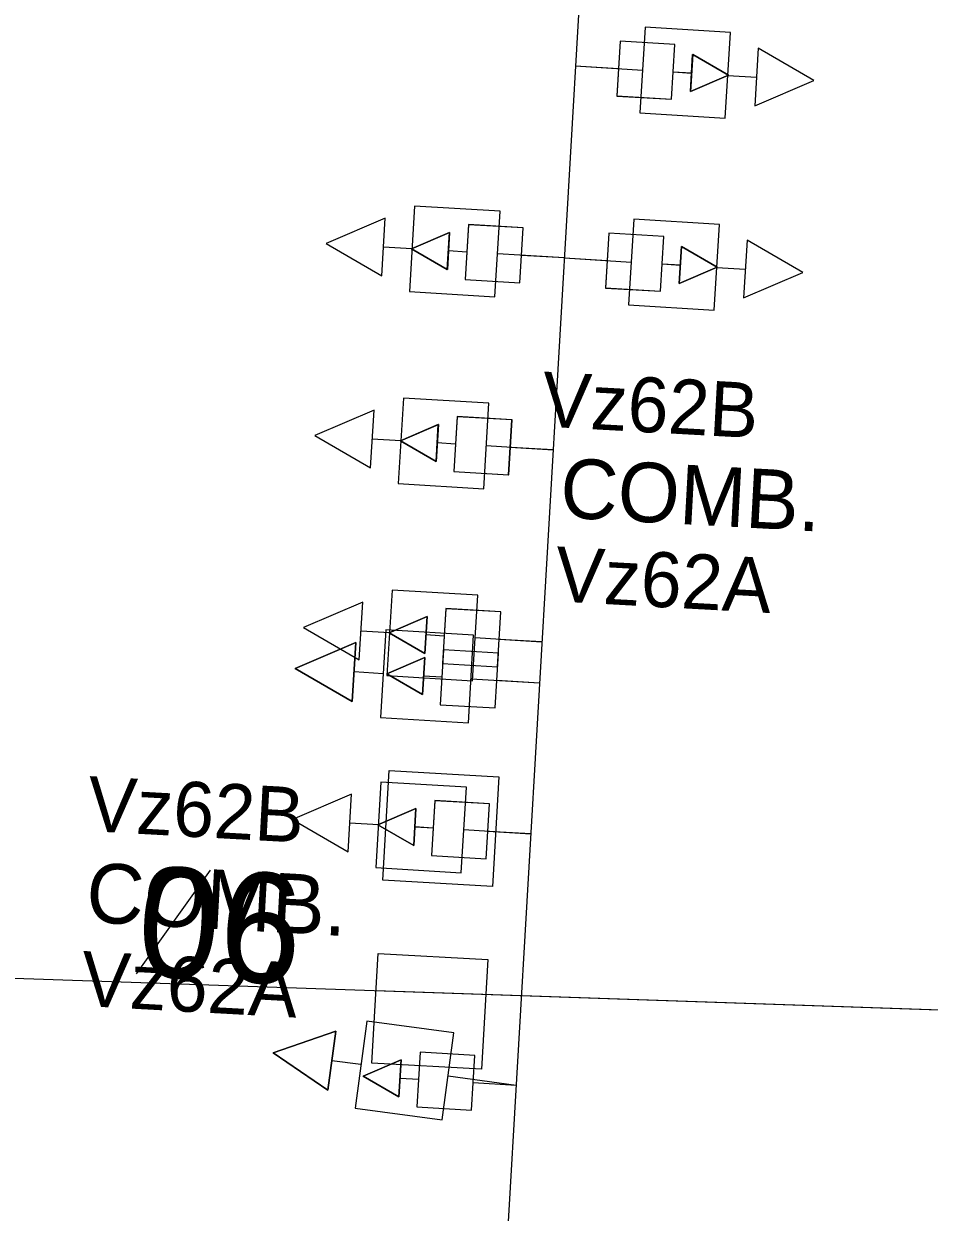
# Model space of a CAD drawing. Extents: x 647787 to 668496, y 640478 to 654412.
# Drawn here: x 661587 to 661636.4, y 647292 to 647356.9 of the extents above; entities that cross this region are included whole.
import ezdxf

# ---------------------------------------------------------------- set-up
doc = ezdxf.new("R2010")
doc.units = 0
for name, color, linetype in [('Default', 7, 'Continuous'), ('TEMP_DETECTION ZONE_Stage 2', 7, 'Continuous'), ('TEMP_DETECTION ZONE_STAGE 3', 7, 'Continuous'), ('TEMP_DETECTION_ZONE_STAGE 4', 7, 'Continuous'), ('TEMP_SIGNAL_HEAD_PED STAGES 1C', 7, 'Continuous'), ('TEMP_SIGNAL_HEAD_STAGE 2', 7, 'Continuous'), ('TEMP_SIGNAL_HEAD_STAGE 2 SHILO', 7, 'Continuous'), ('TEMP_SIGNAL_HEAD_STAGE 3 SHILO', 7, 'Continuous'), ('TEMP_SIGNAL_HEAD_STAGE 4 SHILO', 7, 'Continuous'), ('TEMP_SIGNAL_POLE_STAGE 2-3', 7, 'Continuous')]:
    doc.layers.add(name, color=color, linetype=linetype)

msp = doc.modelspace()

# ---------------------------------------------------------------- linework, layer by layer
at = {"layer": 'Default'}
msp.add_line((661593.14, 647304.985), (661597.182, 647310.641), dxfattribs=at)
msp.add_line((661593.14, 647304.985), (661597.182, 647310.641), dxfattribs=at)
for points in [[(662136.439, 647331.769), (661882.019, 647294.613), (661114.402, 647320.889)], [(661761.55, 647298.737), (661606.212, 647304.054)], [(661761.55, 647298.737), (661606.212, 647304.054)]]:
    msp.add_lwpolyline(points, dxfattribs=at)
at = {"layer": 'TEMP_DETECTION ZONE_STAGE 3'}
for points in [[(661612.588, 647309.755), (661606.598, 647310.095), (661606.938, 647316.085), (661612.928, 647315.745)], [(661611.985, 647299.773), (661605.995, 647300.113), (661606.335, 647306.103), (661612.326, 647305.763)]]:
    msp.add_lwpolyline(points, close=True, dxfattribs=at)
at = {"layer": 'TEMP_DETECTION_ZONE_STAGE 4'}
for points in [[(661612.588, 647309.755), (661606.598, 647310.095), (661606.938, 647316.085), (661612.928, 647315.745)], [(661611.985, 647299.773), (661605.995, 647300.113), (661606.335, 647306.103), (661612.326, 647305.763)]]:
    msp.add_lwpolyline(points, close=True, dxfattribs=at)
at = {"layer": 'TEMP_SIGNAL_HEAD_PED STAGES 1C'}
for points in [[(661612.721, 647319.498), (661612.902, 647322.493), (661609.907, 647322.673), (661609.727, 647319.679)], [(661612.721, 647319.498), (661612.902, 647322.493), (661609.907, 647322.673), (661609.727, 647319.679)], [(661606.807, 647321.358), (661608.758, 647320.227), (661608.88, 647322.246)], [(661606.807, 647321.358), (661608.758, 647320.227), (661608.88, 647322.246)], [(661611.439, 647297.535), (661611.619, 647300.53), (661608.625, 647300.711), (661608.444, 647297.716)], [(661611.439, 647297.535), (661611.619, 647300.53), (661608.625, 647300.711), (661608.444, 647297.716)], [(661605.524, 647299.395), (661607.475, 647298.264), (661607.597, 647300.284)], [(661605.524, 647299.395), (661607.475, 647298.264), (661607.597, 647300.284)]]:
    msp.add_lwpolyline(points, close=True, dxfattribs=at)
for points in [[(661608.88, 647322.246), (661608.758, 647320.227), (661606.807, 647321.358), (661608.88, 647322.246)], [(661608.88, 647322.246), (661608.758, 647320.227), (661606.807, 647321.358), (661608.88, 647322.246)], [(661609.817, 647321.176), (661608.819, 647321.236)], [(661609.817, 647321.176), (661608.819, 647321.236)], [(661615.152, 647320.854), (661612.812, 647320.995)], [(661615.152, 647320.854), (661612.812, 647320.995)], [(661607.597, 647300.284), (661607.475, 647298.264), (661605.524, 647299.395), (661607.597, 647300.284)], [(661607.597, 647300.284), (661607.475, 647298.264), (661605.524, 647299.395), (661607.597, 647300.284)], [(661608.535, 647299.213), (661607.536, 647299.274)], [(661608.535, 647299.213), (661607.536, 647299.274)], [(661613.869, 647298.891), (661611.529, 647299.033)], [(661613.869, 647298.891), (661611.529, 647299.033)]]:
    msp.add_lwpolyline(points, dxfattribs=at)
at = {"layer": 'TEMP_SIGNAL_HEAD_STAGE 2'}
for points in [[(661619.549, 647355.903), (661619.369, 647352.908), (661622.363, 647352.727), (661622.544, 647355.722)], [(661619.549, 647355.903), (661619.369, 647352.908), (661622.363, 647352.727), (661622.544, 647355.722)], [(661619.549, 647355.903), (661619.369, 647352.908), (661622.363, 647352.727), (661622.544, 647355.722)], [(661619.552, 647355.905), (661619.371, 647352.91), (661622.366, 647352.729), (661622.546, 647355.724)], [(661625.464, 647354.043), (661623.513, 647355.174), (661623.391, 647353.155)], [(661625.464, 647354.043), (661623.513, 647355.174), (661623.391, 647353.155)], [(661625.464, 647354.043), (661623.513, 647355.174), (661623.391, 647353.155)], [(661625.466, 647354.045), (661623.515, 647355.176), (661623.393, 647353.156)], [(661608.162, 647344.568), (661610.113, 647343.437), (661610.235, 647345.457)], [(661608.162, 647344.568), (661610.113, 647343.437), (661610.235, 647345.457)], [(661608.162, 647344.568), (661610.113, 647343.437), (661610.235, 647345.457)], [(661608.164, 647344.57), (661610.116, 647343.439), (661610.237, 647345.458)], [(661614.076, 647342.709), (661614.257, 647345.703), (661611.263, 647345.884), (661611.082, 647342.889)], [(661614.076, 647342.709), (661614.257, 647345.703), (661611.263, 647345.884), (661611.082, 647342.889)], [(661614.076, 647342.709), (661614.257, 647345.703), (661611.263, 647345.884), (661611.082, 647342.889)], [(661614.079, 647342.71), (661614.26, 647345.705), (661611.265, 647345.886), (661611.084, 647342.891)], [(661618.937, 647345.421), (661618.757, 647342.426), (661621.751, 647342.245), (661621.932, 647345.24)], [(661618.937, 647345.421), (661618.757, 647342.426), (661621.751, 647342.245), (661621.932, 647345.24)], [(661618.937, 647345.421), (661618.757, 647342.426), (661621.751, 647342.245), (661621.932, 647345.24)], [(661618.94, 647345.422), (661618.759, 647342.428), (661621.753, 647342.247), (661621.934, 647345.242)], [(661624.852, 647343.561), (661622.901, 647344.692), (661622.779, 647342.672)], [(661624.852, 647343.561), (661622.901, 647344.692), (661622.779, 647342.672)], [(661624.852, 647343.561), (661622.901, 647344.692), (661622.779, 647342.672)], [(661624.854, 647343.563), (661622.903, 647344.694), (661622.781, 647342.674)], [(661607.55, 647334.086), (661609.501, 647332.955), (661609.623, 647334.975)], [(661607.55, 647334.086), (661609.501, 647332.955), (661609.623, 647334.975)], [(661607.55, 647334.086), (661609.501, 647332.955), (661609.623, 647334.975)], [(661607.552, 647334.088), (661609.503, 647332.957), (661609.625, 647334.976)], [(661613.464, 647332.226), (661613.645, 647335.221), (661610.651, 647335.402), (661610.47, 647332.407)], [(661613.464, 647332.226), (661613.645, 647335.221), (661610.651, 647335.402), (661610.47, 647332.407)], [(661613.464, 647332.226), (661613.645, 647335.221), (661610.651, 647335.402), (661610.47, 647332.407)], [(661613.467, 647332.228), (661613.648, 647335.223), (661610.653, 647335.404), (661610.472, 647332.409)], [(661612.852, 647321.744), (661613.033, 647324.739), (661610.039, 647324.92), (661609.858, 647321.925)], [(661612.852, 647321.744), (661613.033, 647324.739), (661610.039, 647324.92), (661609.858, 647321.925)], [(661612.852, 647321.744), (661613.033, 647324.739), (661610.039, 647324.92), (661609.858, 647321.925)], [(661612.855, 647321.746), (661613.035, 647324.741), (661610.041, 647324.921), (661609.86, 647321.927)], [(661606.938, 647323.604), (661608.889, 647322.473), (661609.011, 647324.492)], [(661606.938, 647323.604), (661608.889, 647322.473), (661609.011, 647324.492)], [(661606.938, 647323.604), (661608.889, 647322.473), (661609.011, 647324.492)], [(661606.94, 647323.606), (661608.891, 647322.475), (661609.013, 647324.494)], [(661612.24, 647311.262), (661612.421, 647314.257), (661609.426, 647314.437), (661609.246, 647311.443)], [(661612.24, 647311.262), (661612.421, 647314.257), (661609.426, 647314.437), (661609.246, 647311.443)], [(661612.24, 647311.262), (661612.421, 647314.257), (661609.426, 647314.437), (661609.246, 647311.443)], [(661612.243, 647311.264), (661612.423, 647314.258), (661609.429, 647314.439), (661609.248, 647311.445)], [(661606.326, 647313.122), (661608.277, 647311.991), (661608.399, 647314.01)], [(661606.326, 647313.122), (661608.277, 647311.991), (661608.399, 647314.01)], [(661606.326, 647313.122), (661608.277, 647311.991), (661608.399, 647314.01)], [(661606.328, 647313.124), (661608.279, 647311.992), (661608.401, 647314.012)]]:
    msp.add_lwpolyline(points, close=True, dxfattribs=at)
for points in [[(661623.391, 647353.155), (661623.513, 647355.174), (661625.464, 647354.043), (661623.391, 647353.155)], [(661623.391, 647353.155), (661623.513, 647355.174), (661625.464, 647354.043), (661623.391, 647353.155)], [(661623.391, 647353.155), (661623.513, 647355.174), (661625.464, 647354.043), (661623.391, 647353.155)], [(661623.393, 647353.156), (661623.515, 647355.176), (661625.466, 647354.045), (661623.393, 647353.156)], [(661617.119, 647354.547), (661619.459, 647354.405)], [(661617.119, 647354.547), (661619.459, 647354.405)], [(661617.119, 647354.547), (661619.459, 647354.405)], [(661617.121, 647354.549), (661619.461, 647354.407)], [(661622.454, 647354.225), (661623.452, 647354.164)], [(661622.454, 647354.225), (661623.452, 647354.164)], [(661622.454, 647354.225), (661623.452, 647354.164)], [(661622.456, 647354.226), (661623.454, 647354.166)], [(661610.235, 647345.457), (661610.113, 647343.437), (661608.162, 647344.568), (661610.235, 647345.457)], [(661610.235, 647345.457), (661610.113, 647343.437), (661608.162, 647344.568), (661610.235, 647345.457)], [(661610.235, 647345.457), (661610.113, 647343.437), (661608.162, 647344.568), (661610.235, 647345.457)], [(661610.237, 647345.458), (661610.116, 647343.439), (661608.164, 647344.57), (661610.237, 647345.458)], [(661622.779, 647342.672), (661622.901, 647344.692), (661624.852, 647343.561), (661622.779, 647342.672)], [(661622.779, 647342.672), (661622.901, 647344.692), (661624.852, 647343.561), (661622.779, 647342.672)], [(661622.779, 647342.672), (661622.901, 647344.692), (661624.852, 647343.561), (661622.779, 647342.672)], [(661622.781, 647342.674), (661622.903, 647344.694), (661624.854, 647343.563), (661622.781, 647342.674)], [(661611.172, 647344.387), (661610.174, 647344.447)], [(661611.172, 647344.387), (661610.174, 647344.447)], [(661611.172, 647344.387), (661610.174, 647344.447)], [(661611.175, 647344.388), (661610.177, 647344.449)], [(661616.507, 647344.065), (661614.167, 647344.206)], [(661616.507, 647344.065), (661614.167, 647344.206)], [(661616.507, 647344.065), (661614.167, 647344.206)], [(661616.509, 647344.066), (661614.169, 647344.208)], [(661616.507, 647344.065), (661618.847, 647343.923)], [(661616.507, 647344.065), (661618.847, 647343.923)], [(661616.507, 647344.065), (661618.847, 647343.923)], [(661616.509, 647344.066), (661618.849, 647343.925)], [(661621.841, 647343.743), (661622.84, 647343.682)], [(661621.841, 647343.743), (661622.84, 647343.682)], [(661621.841, 647343.743), (661622.84, 647343.682)], [(661621.844, 647343.744), (661622.842, 647343.684)], [(661609.623, 647334.975), (661609.501, 647332.955), (661607.55, 647334.086), (661609.623, 647334.975)], [(661609.623, 647334.975), (661609.501, 647332.955), (661607.55, 647334.086), (661609.623, 647334.975)], [(661609.623, 647334.975), (661609.501, 647332.955), (661607.55, 647334.086), (661609.623, 647334.975)], [(661609.625, 647334.976), (661609.503, 647332.957), (661607.552, 647334.088), (661609.625, 647334.976)], [(661610.56, 647333.904), (661609.562, 647333.965)], [(661610.56, 647333.904), (661609.562, 647333.965)], [(661610.56, 647333.904), (661609.562, 647333.965)], [(661610.563, 647333.906), (661609.564, 647333.967)], [(661615.895, 647333.582), (661613.555, 647333.724)], [(661615.895, 647333.582), (661613.555, 647333.724)], [(661615.895, 647333.582), (661613.555, 647333.724)], [(661615.897, 647333.584), (661613.557, 647333.725)], [(661609.011, 647324.492), (661608.889, 647322.473), (661606.938, 647323.604), (661609.011, 647324.492)], [(661609.011, 647324.492), (661608.889, 647322.473), (661606.938, 647323.604), (661609.011, 647324.492)], [(661609.011, 647324.492), (661608.889, 647322.473), (661606.938, 647323.604), (661609.011, 647324.492)], [(661609.013, 647324.494), (661608.891, 647322.475), (661606.94, 647323.606), (661609.013, 647324.494)], [(661609.948, 647323.422), (661608.95, 647323.483)], [(661609.948, 647323.422), (661608.95, 647323.483)], [(661609.948, 647323.422), (661608.95, 647323.483)], [(661609.951, 647323.424), (661608.952, 647323.484)], [(661615.283, 647323.1), (661612.943, 647323.242)], [(661615.283, 647323.1), (661612.943, 647323.242)], [(661615.283, 647323.1), (661612.943, 647323.242)], [(661615.285, 647323.102), (661612.945, 647323.243)], [(661608.399, 647314.01), (661608.277, 647311.991), (661606.326, 647313.122), (661608.399, 647314.01)], [(661608.399, 647314.01), (661608.277, 647311.991), (661606.326, 647313.122), (661608.399, 647314.01)], [(661608.399, 647314.01), (661608.277, 647311.991), (661606.326, 647313.122), (661608.399, 647314.01)], [(661608.401, 647314.012), (661608.279, 647311.992), (661606.328, 647313.124), (661608.401, 647314.012)], [(661609.336, 647312.94), (661608.338, 647313)], [(661609.336, 647312.94), (661608.338, 647313)], [(661609.336, 647312.94), (661608.338, 647313)], [(661609.338, 647312.942), (661608.34, 647313.002)], [(661614.671, 647312.618), (661612.331, 647312.759)], [(661614.671, 647312.618), (661612.331, 647312.759)], [(661614.671, 647312.618), (661612.331, 647312.759)], [(661614.673, 647312.62), (661612.333, 647312.761)]]:
    msp.add_lwpolyline(points, dxfattribs=at)
at = {"layer": 'TEMP_SIGNAL_HEAD_STAGE 2 SHILO'}
for points in [[(661620.913, 647356.658), (661620.626, 647351.987), (661625.297, 647351.7), (661625.584, 647356.371)], [(661620.913, 647356.658), (661620.626, 647351.987), (661625.297, 647351.7), (661625.584, 647356.371)], [(661630.136, 647353.747), (661627.094, 647355.515), (661626.901, 647352.364)], [(661630.136, 647353.747), (661627.094, 647355.515), (661626.901, 647352.364)], [(661612.715, 647341.949), (661612.997, 647346.621), (661608.326, 647346.903), (661608.044, 647342.231)], [(661612.715, 647341.949), (661612.997, 647346.621), (661608.326, 647346.903), (661608.044, 647342.231)], [(661603.489, 647344.85), (661606.533, 647343.086), (661606.723, 647346.236)], [(661603.489, 647344.85), (661606.533, 647343.086), (661606.723, 647346.236)], [(661620.301, 647346.176), (661620.014, 647341.505), (661624.685, 647341.218), (661624.972, 647345.889)], [(661620.301, 647346.176), (661620.014, 647341.505), (661624.685, 647341.218), (661624.972, 647345.889)], [(661629.524, 647343.265), (661626.482, 647345.033), (661626.289, 647341.882)], [(661629.524, 647343.265), (661626.482, 647345.033), (661626.289, 647341.882)], [(661612.103, 647331.467), (661612.385, 647336.139), (661607.714, 647336.421), (661607.432, 647331.749)], [(661612.103, 647331.467), (661612.385, 647336.139), (661607.714, 647336.421), (661607.432, 647331.749)], [(661602.877, 647334.368), (661605.921, 647332.603), (661606.111, 647335.754)], [(661602.877, 647334.368), (661605.921, 647332.603), (661606.111, 647335.754)], [(661611.491, 647320.984), (661611.773, 647325.656), (661607.102, 647325.938), (661606.82, 647321.266)], [(661611.491, 647320.984), (661611.773, 647325.656), (661607.102, 647325.938), (661606.82, 647321.266)], [(661602.265, 647323.886), (661605.309, 647322.121), (661605.499, 647325.271)], [(661602.265, 647323.886), (661605.309, 647322.121), (661605.499, 647325.271)], [(661610.879, 647310.503), (661611.161, 647315.174), (661606.49, 647315.456), (661606.208, 647310.785)], [(661610.879, 647310.503), (661611.161, 647315.174), (661606.49, 647315.456), (661606.208, 647310.785)], [(661601.653, 647313.404), (661604.696, 647311.639), (661604.887, 647314.79)], [(661601.653, 647313.404), (661604.696, 647311.639), (661604.887, 647314.79)]]:
    msp.add_lwpolyline(points, close=True, dxfattribs=at)
for points in [[(661617.119, 647354.547), (661620.769, 647354.322)], [(661617.119, 647354.547), (661620.769, 647354.322)], [(661625.44, 647354.035), (661626.997, 647353.94)], [(661625.44, 647354.035), (661626.997, 647353.94)], [(661608.185, 647344.567), (661606.628, 647344.661)], [(661608.185, 647344.567), (661606.628, 647344.661)], [(661616.507, 647344.065), (661612.856, 647344.285)], [(661616.507, 647344.065), (661612.856, 647344.285)], [(661616.507, 647344.065), (661620.157, 647343.84)], [(661616.507, 647344.065), (661620.157, 647343.84)], [(661624.828, 647343.553), (661626.385, 647343.457)], [(661624.828, 647343.553), (661626.385, 647343.457)], [(661607.573, 647334.085), (661606.016, 647334.179)], [(661607.573, 647334.085), (661606.016, 647334.179)], [(661615.895, 647333.582), (661612.244, 647333.803)], [(661615.895, 647333.582), (661612.244, 647333.803)], [(661606.961, 647323.602), (661605.404, 647323.696)], [(661606.961, 647323.602), (661605.404, 647323.696)], [(661615.283, 647323.1), (661611.632, 647323.32)], [(661615.283, 647323.1), (661611.632, 647323.32)], [(661606.349, 647313.121), (661604.792, 647313.215)], [(661606.349, 647313.121), (661604.792, 647313.215)], [(661614.671, 647312.618), (661611.02, 647312.839)], [(661614.671, 647312.618), (661611.02, 647312.839)]]:
    msp.add_lwpolyline(points, dxfattribs=at)
at = {"layer": 'TEMP_SIGNAL_HEAD_STAGE 3 SHILO'}
for points in [[(661611.263, 647318.684), (661611.552, 647323.476), (661606.761, 647323.765), (661606.472, 647318.974)], [(661611.263, 647318.684), (661611.552, 647323.476), (661606.761, 647323.765), (661606.472, 647318.974)], [(661601.8, 647321.66), (661604.922, 647319.85), (661605.117, 647323.081)], [(661601.8, 647321.66), (661604.922, 647319.85), (661605.117, 647323.081)], [(661609.832, 647297.012), (661610.471, 647301.769), (661605.714, 647302.408), (661605.075, 647297.651)], [(661609.832, 647297.012), (661610.471, 647301.769), (661605.714, 647302.408), (661605.075, 647297.651)], [(661609.832, 647297.012), (661610.471, 647301.769), (661605.714, 647302.408), (661605.075, 647297.651)], [(661609.832, 647297.012), (661610.471, 647301.769), (661605.714, 647302.408), (661605.075, 647297.651)], [(661600.612, 647300.672), (661603.593, 647298.638), (661604.024, 647301.847)], [(661600.612, 647300.672), (661603.593, 647298.638), (661604.024, 647301.847)], [(661600.612, 647300.672), (661603.593, 647298.638), (661604.024, 647301.847)], [(661600.612, 647300.672), (661603.593, 647298.638), (661604.024, 647301.847)]]:
    msp.add_lwpolyline(points, close=True, dxfattribs=at)
for points in [[(661605.117, 647323.081), (661604.922, 647319.85), (661601.8, 647321.66), (661605.117, 647323.081)], [(661605.117, 647323.081), (661604.922, 647319.85), (661601.8, 647321.66), (661605.117, 647323.081)], [(661606.616, 647321.369), (661605.019, 647321.466)], [(661606.616, 647321.369), (661605.019, 647321.466)], [(661615.152, 647320.854), (661611.408, 647321.08)], [(661615.152, 647320.854), (661611.408, 647321.08)], [(661604.024, 647301.847), (661603.593, 647298.638), (661600.612, 647300.672), (661604.024, 647301.847)], [(661604.024, 647301.847), (661603.593, 647298.638), (661600.612, 647300.672), (661604.024, 647301.847)], [(661604.024, 647301.847), (661603.593, 647298.638), (661600.612, 647300.672), (661604.024, 647301.847)], [(661604.024, 647301.847), (661603.593, 647298.638), (661600.612, 647300.672), (661604.024, 647301.847)], [(661605.394, 647300.03), (661603.809, 647300.243)], [(661605.394, 647300.03), (661603.809, 647300.243)], [(661605.394, 647300.03), (661603.809, 647300.243)], [(661605.394, 647300.03), (661603.809, 647300.243)], [(661613.869, 647298.891), (661610.152, 647299.391)], [(661613.869, 647298.891), (661610.152, 647299.391)], [(661613.869, 647298.891), (661610.152, 647299.391)], [(661613.869, 647298.891), (661610.152, 647299.391)]]:
    msp.add_lwpolyline(points, dxfattribs=at)
at = {"layer": 'TEMP_SIGNAL_HEAD_STAGE 4 SHILO'}
for points in [[(661611.263, 647318.684), (661611.552, 647323.476), (661606.761, 647323.765), (661606.472, 647318.974)], [(661611.263, 647318.684), (661611.552, 647323.476), (661606.761, 647323.765), (661606.472, 647318.974)], [(661601.8, 647321.66), (661604.922, 647319.85), (661605.117, 647323.081)], [(661601.8, 647321.66), (661604.922, 647319.85), (661605.117, 647323.081)], [(661609.832, 647297.012), (661610.471, 647301.769), (661605.714, 647302.408), (661605.075, 647297.651)], [(661609.832, 647297.012), (661610.471, 647301.769), (661605.714, 647302.408), (661605.075, 647297.651)], [(661609.832, 647297.012), (661610.471, 647301.769), (661605.714, 647302.408), (661605.075, 647297.651)], [(661609.832, 647297.012), (661610.471, 647301.769), (661605.714, 647302.408), (661605.075, 647297.651)], [(661600.612, 647300.672), (661603.593, 647298.638), (661604.024, 647301.847)], [(661600.612, 647300.672), (661603.593, 647298.638), (661604.024, 647301.847)], [(661600.612, 647300.672), (661603.593, 647298.638), (661604.024, 647301.847)], [(661600.612, 647300.672), (661603.593, 647298.638), (661604.024, 647301.847)]]:
    msp.add_lwpolyline(points, close=True, dxfattribs=at)
for points in [[(661605.117, 647323.081), (661604.922, 647319.85), (661601.8, 647321.66), (661605.117, 647323.081)], [(661605.117, 647323.081), (661604.922, 647319.85), (661601.8, 647321.66), (661605.117, 647323.081)], [(661606.616, 647321.369), (661605.019, 647321.466)], [(661606.616, 647321.369), (661605.019, 647321.466)], [(661615.152, 647320.854), (661611.408, 647321.08)], [(661615.152, 647320.854), (661611.408, 647321.08)], [(661604.024, 647301.847), (661603.593, 647298.638), (661600.612, 647300.672), (661604.024, 647301.847)], [(661604.024, 647301.847), (661603.593, 647298.638), (661600.612, 647300.672), (661604.024, 647301.847)], [(661604.024, 647301.847), (661603.593, 647298.638), (661600.612, 647300.672), (661604.024, 647301.847)], [(661604.024, 647301.847), (661603.593, 647298.638), (661600.612, 647300.672), (661604.024, 647301.847)], [(661605.394, 647300.03), (661603.809, 647300.243)], [(661605.394, 647300.03), (661603.809, 647300.243)], [(661605.394, 647300.03), (661603.809, 647300.243)], [(661605.394, 647300.03), (661603.809, 647300.243)], [(661613.869, 647298.891), (661610.152, 647299.391)], [(661613.869, 647298.891), (661610.152, 647299.391)], [(661613.869, 647298.891), (661610.152, 647299.391)], [(661613.869, 647298.891), (661610.152, 647299.391)]]:
    msp.add_lwpolyline(points, dxfattribs=at)
at = {"layer": 'TEMP_SIGNAL_POLE_STAGE 2-3'}
msp.add_line((661619.528, 647395.804), (661611.634, 647260.615), dxfattribs=at)
msp.add_line((661619.528, 647395.804), (661611.634, 647260.615), dxfattribs=at)

# ---------------------------------------------------------------- texts
at = {"layer": 'Default'}
msp.add_text('06', height=6, rotation=356.61808, dxfattribs=at).set_placement((661593.075, 647304.901))
msp.add_text('06', height=6, rotation=356.61808, dxfattribs=at).set_placement((661593.075, 647304.901))
at = {"layer": 'TEMP_DETECTION ZONE_Stage 2'}
for s, height, p in [('Vz62B', 3, (661615.221, 647334.87)), ('COMB.', 3.25, (661616.216, 647329.906)), ('Vz62A', 3, (661615.942, 647325.325))]:
    msp.add_text(s, height=height, rotation=356.86587, dxfattribs=at).set_placement(p)
at = {"layer": 'TEMP_DETECTION ZONE_STAGE 3'}
for s, height, p in [('Vz62B', 3, (661590.405, 647312.784)), ('COMB.', 3.25, (661590.332, 647307.82)), ('Vz62A', 3, (661590.058, 647303.239))]:
    msp.add_text(s, height=height, rotation=356.86587, dxfattribs=at).set_placement(p)
at = {"layer": 'TEMP_DETECTION_ZONE_STAGE 4'}
for s, height, p in [('Vz62B', 3, (661590.405, 647312.784)), ('COMB.', 3.25, (661590.332, 647307.82)), ('Vz62A', 3, (661590.058, 647303.239))]:
    msp.add_text(s, height=height, rotation=356.86587, dxfattribs=at).set_placement(p)

doc.saveas('drawing.dxf')
